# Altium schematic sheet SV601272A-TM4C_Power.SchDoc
size 431 x 279 mm; Date: Not shown in title block; ApprovedBy: Not shown in title block; CheckedBy: Not shown in title block; Author: Not shown in title block; CompanyName: Not shown in title block; Engineer: Not shown in title block; Organization: Not shown in title block; Address1: Not shown in title block; Address2: Not shown in title block; Address3: Not shown in title block; Address4: Not shown in title block; DocumentNumber: 11; Revision: Use project parameter SCH_Rev; SheetNumber: 11; SheetTotal: 11; PageSetup: Record=PageOptions¦CenterHorizontal=True¦CenterVertical=True¦PrintScale=1.00¦XCorrection=1.00¦YCorrection=1.00¦PrintKind=0¦BorderSize=5000000¦LeftOffset=0¦BottomOffset=0¦Orientation=2¦PaperLength=1000¦PaperWidth=1000¦Scale=100¦PaperSource=15¦PrintQuality=600¦MediaType=1¦DitherType=10¦PaperKind=Letter¦PrintScaleMode=1
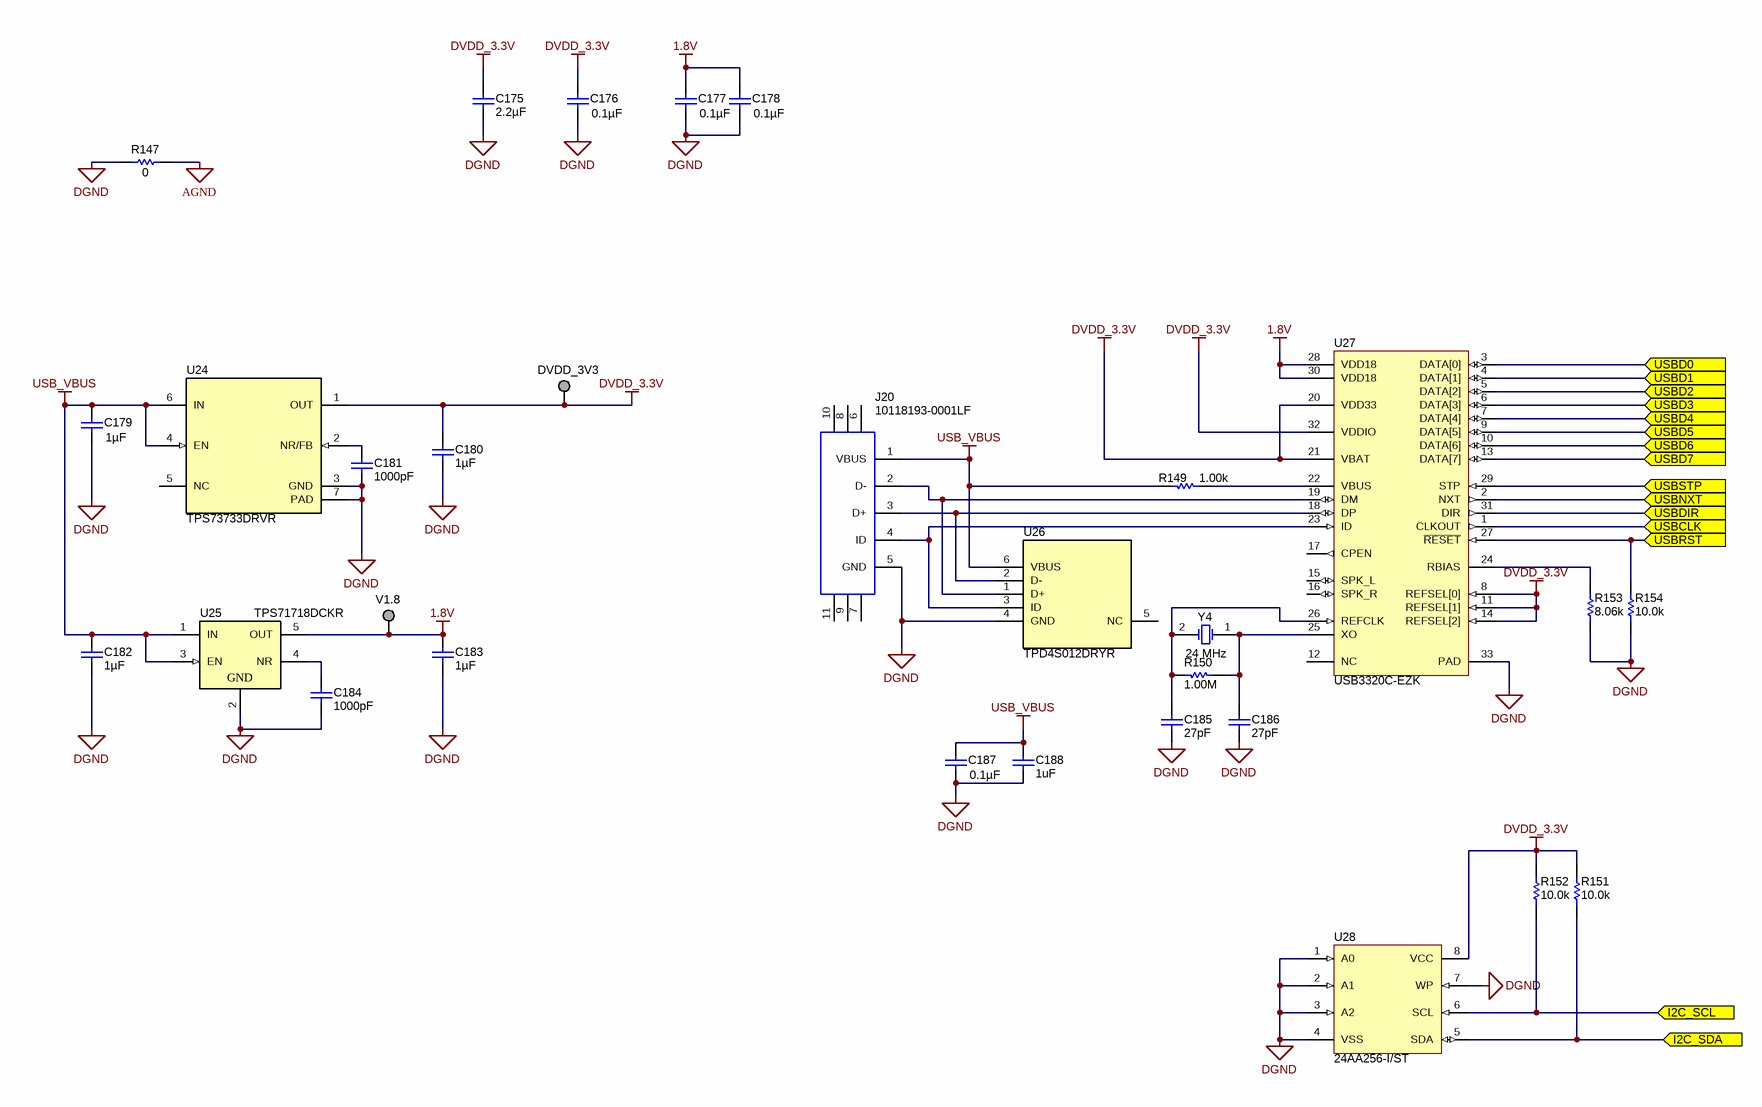
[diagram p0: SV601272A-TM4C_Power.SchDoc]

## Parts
C175  ValueDisplayed: 2.2µF  [0603]  (hidden comment: GRM188R6YA225KA12D)
C176  ValueDisplayed: 0.1µF  [0603]  (hidden comment: 06033C104JAT2A)
C177  ValueDisplayed: 0.1µF  [0603]  (hidden comment: 06033C104JAT2A)
C178  ValueDisplayed: 0.1µF  [0603]  (hidden comment: 06033C104JAT2A)
C179  ValueDisplayed: 1µF  [0603]  (hidden comment: GRM188R71E105KA12D)
C180  ValueDisplayed: 1µF  [0603]  (hidden comment: GRM188R71E105KA12D)
C181  ValueDisplayed: 1000pF  [0603]  (hidden comment: 06031C102JAT2A)
C182  ValueDisplayed: 1µF  [0603]  (hidden comment: GRM188R71E105KA12D)
C183  ValueDisplayed: 1µF  [0603]  (hidden comment: GRM188R71E105KA12D)
C184  ValueDisplayed: 1000pF  [0603]  (hidden comment: 06031C102JAT2A)
C185  ValueDisplayed: 27pF  [0603]  (hidden comment: 06035A270JAT2A)
C186  ValueDisplayed: 27pF  [0603]  (hidden comment: 06035A270JAT2A)
C187  ValueDisplayed: 0.1µF  [0603]  (hidden comment: 06033C104JAT2A)
C188  ValueDisplayed: 1uF  [0603]  (hidden comment: Capacitor)
DVDD_3V3  Pogo Pad  [PogoPad]  (value not drawn)  (no BOM)
J20  10118193-0001LF  [FCI_10118193-0001LF]
R147  ValueDisplayed: 0  [0603]  (hidden comment: Resistor)
R149  ValueDisplayed: 1.00k  [0603]  (hidden comment: CRCW06031K00FKEA)
R150  ValueDisplayed: 1.00M  [0603]  (hidden comment: CRCW06031M00FKEA)
R151  ValueDisplayed: 10.0k  [0603]  (hidden comment: CRCW060310K0FKEA)
R152  ValueDisplayed: 10.0k  [0603]  (hidden comment: CRCW060310K0FKEA)
R153  ValueDisplayed: 8.06k  [0603]  (hidden comment: CRCW06038K06FKEA)
R154  ValueDisplayed: 10.0k  [0603]  (hidden comment: CRCW060310K0FKEA)
U24  TPS73733DRVR  [DRV0006A]
U25  TPS71718DCKR  [DCK0005A_N]
U26  TPD4S012DRYR  [DRY0006A]
U27  USB3320C-EZK  [Microchip_32QFN-3304-5x5B]
U28  24AA256-I/ST  [TSSOP-8]
V1.8  Pogo Pad  [PogoPad]  (value not drawn)  (no BOM)
Y4  Frequency: 24 MHz  [XTAL_ABM3]  (hidden comment: ABM3-24.000MHZ-D2Y-T)

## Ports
I2C_SCL, I2C_SDA, USBCLK, USBD0, USBD1, USBD2, USBD3, USBD4, USBD5, USBD6, USBD7, USBDIR, USBNXT, USBRST, USBSTP

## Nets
1.8V: C177.2 C178.2 C183.1 U25.5(OUT) U27.28(VDD18) U27.30(VDD18) V1.8.1
AGND: R147.2
DGND: C175.2 C176.1 C177.1 C178.1 C179.2 C180.2 C181.2 C182.2 C183.2 C184.2 C185.1 C186.1 C187.1 C188.2 J20.5(GND) R147.1 R153.1 R154.1 U24.3(GND) U24.7(PAD) U25.2(GND) U26.4(GND) U27.33(PAD) U28.1(A0) U28.2(A1) U28.3(A2) U28.4(VSS) U28.7(WP)
DVDD_3.3V: C175.1 C176.2 C180.1 DVDD_3V3.1 R151.2 R152.2 U24.1(OUT) U27.8(REFSEL[0]) U27.11(REFSEL[1]) U27.14(REFSEL[2]) U27.20(VDD33) U27.21(VBAT) U27.32(VDDIO) U28.8(VCC)
USB_VBUS: C179.1 C182.1 C187.2 C188.1 J20.1(VBUS) R149.2 U24.4(EN) U24.6(IN) U25.1(IN) U25.3(EN) U26.6(VBUS)
I2C_SCL: R152.1 U28.6(SCL) ; port I2C_SCL
I2C_SDA: R151.1 U28.5(SDA) ; port I2C_SDA
USBCLK: U27.1(CLKOUT) ; port USBCLK
USBD0: U27.3(DATA[0]) ; port USBD0
USBD1: U27.4(DATA[1]) ; port USBD1
USBD2: U27.5(DATA[2]) ; port USBD2
USBD3: U27.6(DATA[3]) ; port USBD3
USBD4: U27.7(DATA[4]) ; port USBD4
USBD5: U27.9(DATA[5]) ; port USBD5
USBD6: U27.10(DATA[6]) ; port USBD6
USBD7: U27.13(DATA[7]) ; port USBD7
USBDIR: U27.31(DIR) ; port USBDIR
USBNXT: U27.2(NXT) ; port USBNXT
USBRST: R154.2 U27.27(~{RESET}) ; port USBRST
USBSTP: U27.29(STP) ; port USBSTP
NetC181_1: C181.1 U24.2(NR/FB)
NetC184_1: C184.1 U25.4(NR)
NetC185_2: C185.2 R150.2 U27.26(REFCLK) Y4.2(OSC2)
NetC186_2: C186.2 R150.1 U27.25(XO) Y4.1(OSC1)
NetJ20_2: J20.2(D-) U26.1(D+) U27.19(DM)
NetJ20_3: J20.3(D+) U26.2(D-) U27.18(DP)
NetJ20_4: J20.4(ID) U26.3(ID) U27.23(ID)
NetR149_1: R149.1 U27.22(VBUS)
NetR153_2: R153.2 U27.24(RBIAS)

Not connected (* = marked no-connect by the designer): J20 6 7 8 9 10 11; U24 5(NC); U26 5(NC); U27 12(NC) 15(SPK_L) 16(SPK_R) 17(CPEN)

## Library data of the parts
C175 = GRM188R6YA225KA12D: CAP, CERM, 2.2 µF, 35 V, +/- 10%, X5R, 0603; Manufacturer: MuRata; Polarized: N; CompType: Capacitor; Value: 2.2uF; U/M: EA; Cap_F: 0.0000022; Tolerance_%: 10; Value1: Unknown; VDC_V: 35; Value2: 35V; TaMin_C: -55; TaMax_C: 85; AEC Category: Q200
C176-C178 C187 = 06033C104JAT2A: CAP, CERM, 0.1 µF, 25 V, +/- 5%, X7R, 0603; Manufacturer: AVX; Polarized: N; CompType: Capacitor; Value: 0.1uF; U/M: EA; Cap_F: 0.0000001; Tolerance_%: 5; ESR_ohm: 0.05; Value1: 0.05 ohm; VDC_V: 25; Value2: 25V; TaMin_C: -55; TaMax_C: 125; AEC Category: Q200
C179 C180 C182 C183 = GRM188R71E105KA12D: CAP, CERM, 1 µF, 25 V, +/- 10%, X7R, 0603; Manufacturer: MuRata; Polarized: N; CompType: Capacitor; Value: 1uF; U/M: EA; Cap_F: 0.000001; Tolerance_%: 10; Value1: Unknown; VDC_V: 25; Value2: 25V; TaMin_C: -55; TaMax_C: 125; AEC Category: Q200
C181 C184 = 06031C102JAT2A: CAP, CERM, 1000 pF, 100 V, +/- 5%, X7R, 0603; Manufacturer: AVX; Polarized: N; CompType: Capacitor; Value: 1000pF; U/M: EA; Cap_F: 0.000000001; Tolerance_%: 5; ESR_ohm: 0.276; Value1: 0.276 ohm; VDC_V: 100; Value2: 100V; TaMin_C: -55; TaMax_C: 125; AEC Category: Q200
C185 C186 = 06035A270JAT2A: CAP, CERM, 27 pF, 50 V, +/- 5%, C0G/NP0, 0603; Manufacturer: AVX; Polarized: N; CompType: Capacitor; Value: 27pF; U/M: EA; Cap_F: 0.000000000027; Tolerance_%: 5; ESR_ohm: 0.232; Value1: 0.232 ohm; VDC_V: 50; Value2: 50V; TaMin_C: -55; TaMax_C: 125; AEC Category: Q200
C188 = CMP-0007405-4: CAP, CERM, 1 uF, 25 V, +/- 10%, X7R, 0603; PartNumber: GRM188R71E105KA12D; Manufacturer: MuRata; Polarized: N; Value: 1uF; U/M: EA; Cap_F: 1µF; Value1: Unknown; VDC_V: 25V; TaMin_C: -55°C; TaMax_C: 125°C; AEC Category: Q200; SizeArea_mm2: 1.28; SizeAreaWB_mm2: 4.68; SizeX_mm: 1.6; SizeY_mm: 0.8; SizeZ_mm: 1
DVDD_3V3 V1.8 = PogoPad: Pad for Pogo Pin Connector; SymbolCreator: codlsc
J20 = CMP-0065029-1: Connector, Receptacle, USB Micro B, R/A, SMT; Manufacturer: FCI; CNHeader: False; Gender: Female; Row_Count: 1; Pitch_mm: 0.65; ContactFinish: Gold; CT: True
R147 = CMP-0025874-3: RES, 0, 5%, 0.1 W, 0603; PartNumber: ERJ-3GEY0R00V; Manufacturer: Panasonic; Value: 0; Value_Code: 0000; Power_W: 100mW; Value2: 0.1W; VDC_V: 50V; TempCo: 600 ppm/C; EIA_Code: E24; U/M: EA; AEC Category: Q200; SizeArea_mm2: 1.28; SizeX_mm: 1.6; SizeY_mm: 0.8; SizeZ_mm: 1
R149 = CRCW06031K00FKEA: RES, 1.00 k, 1%, 0.1 W, 0603; Manufacturer: Vishay-Dale; CompType: Resistor; Value: 1.00k; Res_ohm: 1000; Value_Code: 1k00; Tolerance_%: 1; Power_W: 0.1; Value2: 0.1W; VDC_V: 75; TempCo: 100 ppm/C; EIA_Code: E96; U/M: EA; AEC Category: Q200
R150 = CRCW06031M00FKEA: RES, 1.00 M, 1%, 0.1 W, 0603; Manufacturer: Vishay-Dale; CompType: Resistor; Value: 1.00Meg; Res_ohm: 1000000; Value_Code: 1M00; Tolerance_%: 1; Power_W: 0.1; Value2: 0.1W; VDC_V: 75; TempCo: 100 ppm/C; EIA_Code: E96; U/M: EA; AEC Category: Q200
R151 R152 R154 = CRCW060310K0FKEA: RES, 10.0 k, 1%, 0.1 W, 0603; Manufacturer: Vishay-Dale; CompType: Resistor; Value: 10.0k; Res_ohm: 10000; Value_Code: 10k0; Tolerance_%: 1; Power_W: 0.1; Value2: 0.1W; VDC_V: 75; TempCo: 100 ppm/C; EIA_Code: E96; U/M: EA; AEC Category: Q200
R153 = CRCW06038K06FKEA: RES, 8.06 k, 1%, 0.1 W, 0603; Manufacturer: Vishay-Dale; CompType: Resistor; Value: 8.06k; Res_ohm: 8060; Value_Code: 8k06; Tolerance_%: 1; Power_W: 0.1; Value2: 0.1W; VDC_V: 75; TempCo: 100 ppm/C; EIA_Code: E96; U/M: EA; AEC Category: Q200
U24 = TPS73733DRVR: 1-A Low-Dropout Regulator With Reverse Current Protection, DRV0006A; Manufacturer: Texas Instruments; Alternate PartNumber: TPS73733DRVT; SymbolCreator: a0411947; CompType: IC; U/M: EA
U25 = TPS71718DCKR: Single Output High PSRR LDO, 150 mA, Fixed 1.8 V Output, 2.5 to 6.5 V Input, with Low IQ, 5-pin SC70 (DCK), -40 to 85 degC, Green (RoHS & no Sb/Br); Manufacturer: Texas Instruments; Alternate PartNumber: Equivalent; Accuracy(%): 3; Fixed Output Options(V): 1.8; Iout(Max)(A): 0.15; Iq(Typ)(mA): 0.05; SubFamily: Single Channel LDO; Vdo(Typ)(mV): 170; Vin(Max)(V): 6.5; Vin(Min)(V): 2.5
U26 = CMP-0043122-2: USB ESD Solution with Power Clamp, 4 Channels, -40 to +85 degC, 6-pin SON (DRY), Green (RoHS & no Sb/Br); Manufacturer: Texas Instruments; IO Leakage Current(nA): 10; USB High Speed: TRUE; Breakdown Voltage(Min)(V): 6; IO Capacitance(Typ)(pF): 0.8; AEC Category: Q200; AEC Qualified: N; CompType: IC; SizeAreaWB_mm2: 4.9; SizeArea_mm2: 1.45; SizeX_mm: 1.0; SizeZ_mm: 0.6
U27 = USB3320C-EZK: Highly Integrated Full Featured Hi-Speed USB 2.0 ULPI Transceiver, QFN-32; Manufacturer: Microchip; SymbolCreator: Altium
U28 = 24AA256-I/ST: 256K I2C™ CMOS Serial EEPROM, TSSOP-8; Manufacturer: Microchip; SymbolCreator: a0411947
Y4 = ABM3-24.000MHZ-D2Y-T: Crystal, 24 MHz, 18 pF, SMD; Manufacturer: Abracon Corportation; SymbolCreator: a0412235; U/M: EA; TaMin_C: -40; TaMax_C: 85; Frequency Stability: ±30ppm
